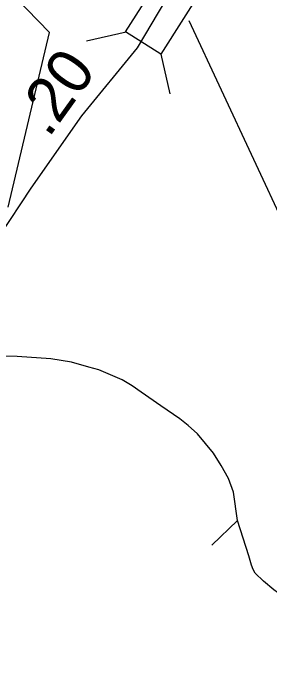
# Model space of a CAD drawing. Extents: x 1662474 to 1856135, y 779280 to 917889.
# Drawn here: x 1725630 to 1726341, y 810656 to 812500 of the extents above; entities that cross this region are included whole.
import ezdxf

# ---------------------------------------------------------------- set-up
doc = ezdxf.new("R2010")
doc.units = 0
for name, color, linetype in [('Exist Boundary Political City Limit New', 7, 'Continuous'), ('Exist Road Non-System Type 51', 7, 'Continuous'), ('Exist Road Secondary Mileage Tenths English Label', 7, 'Continuous'), ('Exist Road Secondary Structure Standard Bridge CELL', 7, 'Continuous'), ('Exist Road Secondary Structure Standard Bridge Number Label', 7, 'Continuous'), ('Exist Road Secondary Type 51 Attributed', 7, 'Continuous'), ('Map Preparation Boundary City Limit Buffer Line', 7, 'Continuous')]:
    doc.layers.add(name, color=color, linetype=linetype)

msp = doc.modelspace()

# ---------------------------------------------------------------- linework, layer by layer
at = {"layer": 'Exist Boundary Political City Limit New'}
msp.add_lwpolyline([(1725615.5, 811961.9), (1725730.1, 812446.8), (1725573.2, 812608.6)], dxfattribs=at)
at = {"layer": 'Exist Road Non-System Type 51'}
msp.add_line((1726251.4, 811092.9), (1726180.7, 811023.8), dxfattribs=at)
for points in [[(1726251.4, 811092.9), (1726240.2, 811170.9), (1726226.5, 811209.3), (1726206.9, 811245.4), (1726184.9, 811279.7), (1726140.4, 811333.1), (1726114.9, 811356), (1726092, 811374.5), (1726039.3, 811411.3), (1725984.9, 811449.2), (1725959.3, 811466.5), (1725931.7, 811482.8), (1725867.3, 811510.4), (1725839.2, 811518.5), (1725790.9, 811531.6), (1725733.7, 811541.3), (1725640, 811548.1), (1725534, 811549), (1725413.3, 811547.7)], [(1726768, 810605.5), (1726731.1, 810665.3), (1726723.4, 810675.3), (1726715.7, 810682.7), (1726708.6, 810690.4), (1726695.4, 810699.5), (1726643.6, 810721.9), (1726595.9, 810748.1), (1726538.2, 810782.8), (1726476.7, 810825.4), (1726417.3, 810857.8), (1726373.2, 810885.9), (1726352.5, 810900.5), (1726323.8, 810924.4), (1726300.9, 810946.8), (1726295.2, 810956.8), (1726290.2, 810968.7), (1726283.2, 810994.4), (1726251.4, 811092.9)]]:
    msp.add_lwpolyline(points, dxfattribs=at)
at = {"layer": 'Exist Road Secondary Structure Standard Bridge CELL'}
for p, q in [((1725943.1, 812447.3), (1725832.7, 812422.4)), ((1726038.8, 812386.8), (1726063.7, 812276.4))]:
    msp.add_line(p, q, dxfattribs=at)
msp.add_lwpolyline([(1726171.7, 812596), (1726039.2, 812386.5), (1725941.4, 812448.4), (1726073.8, 812657.9)], close=True, dxfattribs=at)
at = {"layer": 'Exist Road Secondary Structure Standard Bridge Number Label'}
msp.add_line((1726116.3, 812480.1), (1726963.5, 810661.6), dxfattribs=at)
at = {"layer": 'Exist Road Secondary Type 51 Attributed'}
msp.add_lwpolyline([(1726051.9, 812536.4), (1725973.1, 812404.1), (1725819.1, 812215.5), (1725678.5, 812014.9), (1725590, 811882.1)], dxfattribs=at)
at = {"layer": 'Map Preparation Boundary City Limit Buffer Line'}
msp.add_lwpolyline([(1725615.5, 811961.9), (1725730.1, 812446.8), (1725573.2, 812608.6)], dxfattribs=at)

# ---------------------------------------------------------------- texts
at = {"layer": 'Exist Road Secondary Mileage Tenths English Label'}
msp.add_text('.20', height=125, rotation=54.387, dxfattribs=at).set_placement((1725727.6, 812152.1))

doc.saveas('drawing.dxf')
